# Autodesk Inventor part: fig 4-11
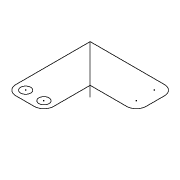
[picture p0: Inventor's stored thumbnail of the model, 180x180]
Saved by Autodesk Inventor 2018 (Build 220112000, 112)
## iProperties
Created: 2005-02
Part Number: fig 4-11
Document SubType Name: Modeling
Designer: CADCIM
Manufacturer: Standard
Standards Organization: Custom
Density: 1 g/cm^3
Material: Generic
Appearance: Default
Author: CADCIM
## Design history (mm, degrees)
sketch "Sketch1"
  geometry: L1 (5.141, 24.979)-(-32.827, 24.979); L2 (-32.827, 24.979)-(-32.827, -12.989); L3 (-27.827, -17.989)-(-18.492, -17.989); L4 (-13.492, -12.989)-(-13.492, 5.644); L5 (-13.492, 5.644)-(5.141, 5.644); L6 (10.141, 10.644)-(10.141, 19.979); L7 (-32.827, 24.979)-(-8.203, 0.354); C1 r 2.58 at (-27.827, -12.989); C2 r 2.58 at (-18.492, -12.989); A1 r 5 centre (-27.827, -12.989) between (-32.827, -12.989) and (-27.827, -17.989); A2 r 5 centre (-18.492, -12.989) between (-18.492, -17.989) and (-13.492, -12.989); A3 r 5 centre (5.141, 10.644) between (5.141, 5.644) and (10.141, 10.644); A4 r 5 centre (5.141, 19.979) between (10.141, 19.979) and (5.141, 24.979)
  constraints: 14 end point, 8 point on circle, 8 tangent, 6 centre point, 4 equal radius, 4 parallel, 3 perpendicular, 2 coincident, 1 horizontal, 1 point on line
